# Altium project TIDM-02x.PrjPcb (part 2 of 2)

## Sheet TIDA-05x_Hardware.SchDoc
size 431 x 279 mm; Date: Not shown in title block; ApprovedBy: Not shown in title block; CheckedBy: Not shown in title block; Author: Not shown in title block; CompanyName: Not shown in title block; Engineer: Not shown in title block; Organization: Not shown in title block; Address1: Not shown in title block; Address2: Not shown in title block; Address3: Not shown in title block; Address4: Not shown in title block; DocumentNumber: 3; Revision: Use project parameter SCH_Rev; SheetNumber: 3; SheetTotal: 3; PageSetup: Record=PageOptions¦CenterHorizontal=True¦CenterVertical=True¦PrintScale=1.00¦XCorrection=1.00¦YCorrection=1.00¦PrintKind=0¦BorderSize=5000000¦LeftOffset=0¦BottomOffset=0¦Orientation=2¦PaperLength=1000¦PaperWidth=1000¦Scale=100¦PaperSource=15¦PrintQuality=600¦MediaType=1¦DitherType=10¦PaperKind=Letter¦PrintScaleMode=1
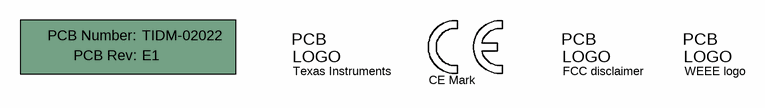
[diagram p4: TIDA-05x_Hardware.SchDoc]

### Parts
!PCB1  Printed Circuit Board  (value not drawn)  (mechanical)
Logo3  CE Mark  [CE_Mark_5mm]  (no BOM)
Logo4  Texas Instruments  [TI_Stacked_Overlay_Small_Vertical]  (no BOM)
Logo5  FCC disclaimer  [FCC_disclaimer_stacked]  (no BOM)
Logo6  WEEE logo  [WEEE_Minimum]  (no BOM)

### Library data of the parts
!PCB1 = CMP-0003618-2: Manufacturer: Any; PartNumber: TIDM-02022
Logo3 = CMP-0074844-1: SymbolCreator: a0412235
Logo4 = CMP-0074838-1: Texas Instrument Corporate Signature; SymbolCreator: a0412235; Lib Reference: TI_Logo; Library Reference: Logo
Logo5 = CMP-0074847-1: FCC_disclaimer; Library Reference: Logo
Logo6 = CMP-0074769-1

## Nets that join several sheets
3V3: Control (9 pins), MCU_Support (6 pins), PowerStage (18 pins)
5V: Control (9 pins), PowerStage (16 pins)
GND: Control (32 pins), MCU_Support (16 pins), PowerStage (55 pins)
PGND: Control (C111.2 R68.1), PowerStage (62 pins)
VIN: Control (5 pins), PowerStage (54 pins)
EPWM1A: MCU_Support (U18.47), PowerStage (R96.2 U1.3)
EPWM1B: MCU_Support (U18.46), PowerStage (R9.1)
EPWM2A: MCU_Support (U18.45), PowerStage (R97.2 U2.3)
EPWM2B: MCU_Support (U18.44), PowerStage (R11.1)
EPWM3A: MCU_Support (U18.43), PowerStage (R98.2 U3.3)
EPWM3B: MCU_Support (U18.55), PowerStage (R13.1)
EPWM4A: MCU_Support (U18.1), PowerStage (R99.2 U4.3)
EPWM4B: MCU_Support (U18.52), PowerStage (R15.1)
FLTGAN: MCU_Support (U18.51), PowerStage (U13.11)
IPh1: Control (U18.12), PowerStage (C89.1 R37.2)
IPh2: Control (U18.22), PowerStage (C90.1 R38.2)
IPh3: Control (U18.11), PowerStage (C91.1 R39.2)
IPh4: Control (U18.17), PowerStage (C92.1 R40.2)
P_GOOD: Control (J8.7), MCU_Support (R56.1 U18.48)
VOUT: Control (C107.2 R66.1), PowerStage (15 pins)

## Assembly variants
001: not fitted R45 R51
LMG3100: not fitted R1 R2 R3 R4 R5 R6 R7 R8 R10 R12 R14 R16 R17 R18 R19 R20 R21 R22 R23 R24 R71 R72 R73 R74 R75 R76 R77 R78 R79 R80 R81 R82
